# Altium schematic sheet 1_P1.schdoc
size 431 x 309 mm; Symbol: Sheet-Symbol_A4; Device: Sheet-Symbol_A4; @Page Name: P1; @Create Date: 2022-12-06; @Page Count: 3; @Page No: 1; @Project Name: MainBoard; @Schematic Name: Schematic1; @Update Date: 2022-12-29 15:32:21; Company: 嘉立创EDA; Page Size: A4; Version: V1.0
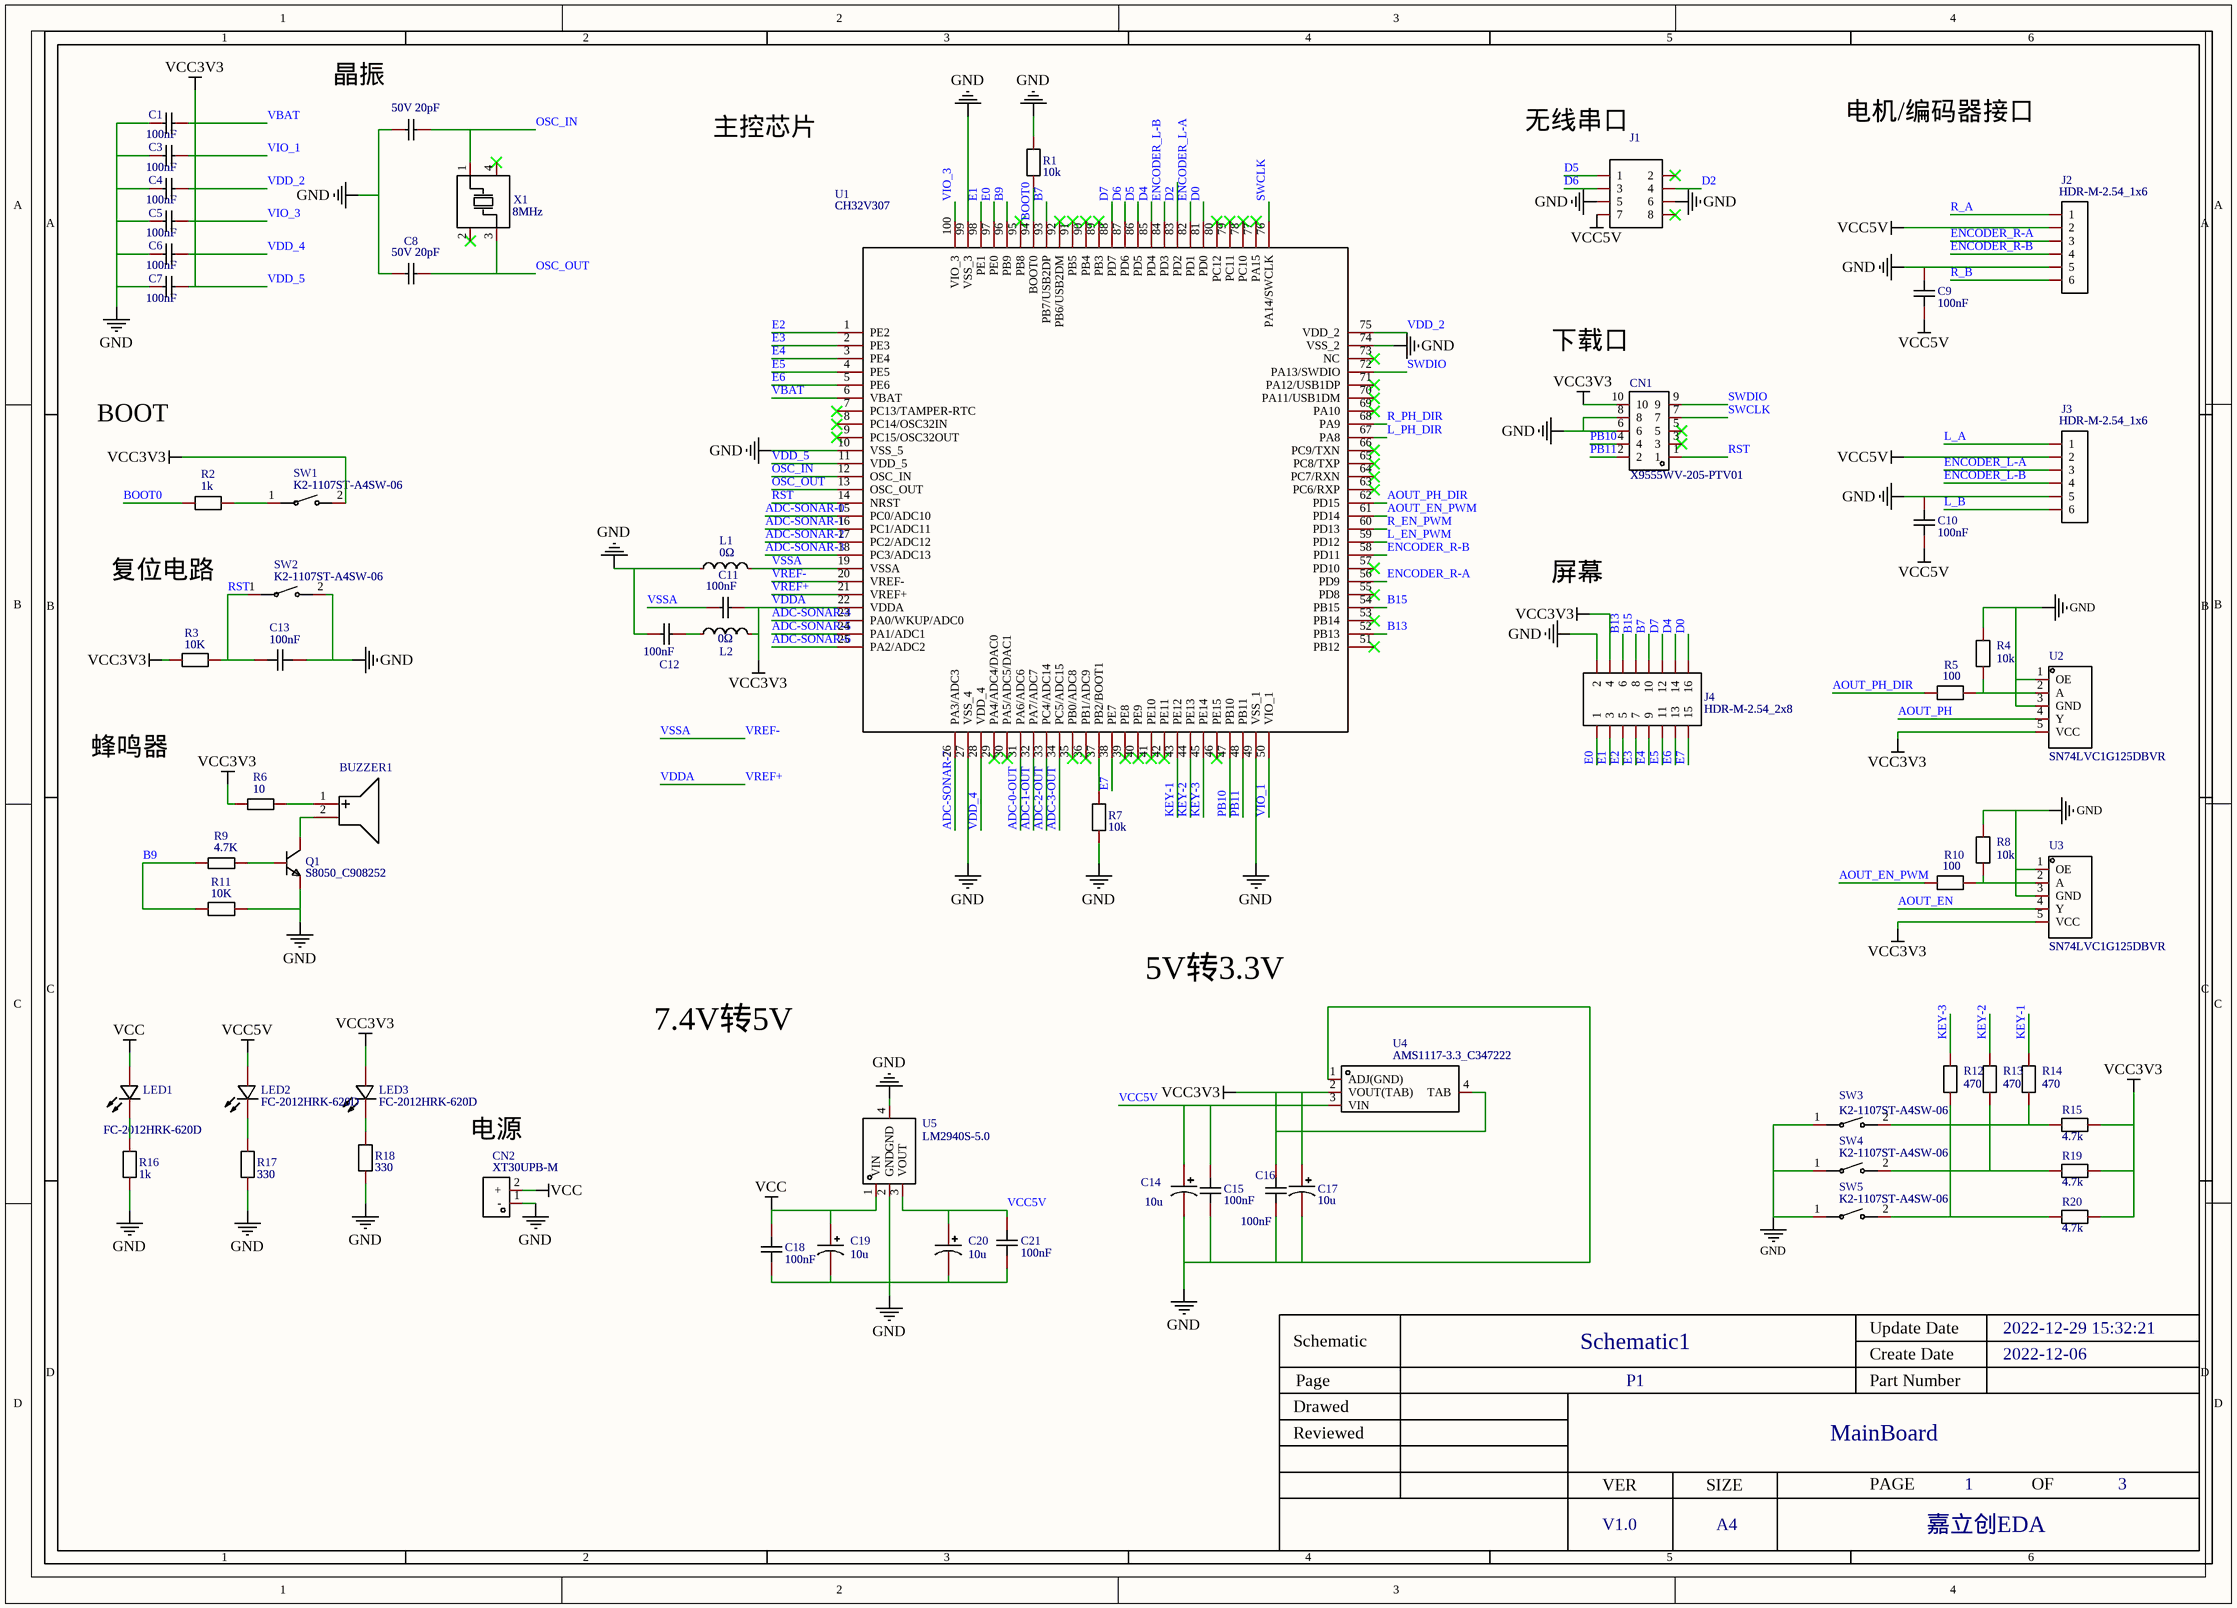
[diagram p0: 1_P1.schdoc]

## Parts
BUZZER1  2900Hz  [BUZ-TH_BD9.0-P5.00-D0.6-L-FD]  (value not drawn)
C1  100nF  [C0603]
C2  50V 20pF  [C0603]
C3  100nF  [C0603]
C4  100nF  [C0603]
C5  100nF  [C0603]
C6  100nF  [C0603]
C7  100nF  [C0603]
C8  50V 20pF  [C0603]
C9  100nF  [C0603]
C10  100nF  [C0603]
C11  100nF  [C0603]
C12  100nF  [C0603]
C13  100nF  [C0603]
C14  10u  [CASE-A_3216]
C15  100nF  [C0603]
C16  100nF  [C0603]
C17  10u  [CASE-A_3216]
C18  100nF  [C0603]
C19  10u  [CASE-A_3216]
C20  10u  [CASE-A_3216]
C21  100nF  [C0603]
CN1  X9555WV-205-PTV01  [CONN-TH_X9555WV-2-05-PTV01]
CN2  XT30UPB-M  [CONN-TH_XT30UPB-M]
J1  HDR-M-2.54_2x4  [HDR-M-2.54_2X4]  (value not drawn)
J2  HDR-M-2.54_1x6  [HDR-M-2.54_1X6]
J3  HDR-M-2.54_1x6  [HDR-M-2.54_1X6]
J4  HDR-M-2.54_2x8  [HDR-M-2.54_2X8]
L1  0Ω  [L0603]
L2  0Ω  [L0603]
LED1  FC-2012HRK-620D  [LED0805-RD_RED]
LED2  FC-2012HRK-620D  [LED0805-RD_RED]
LED3  FC-2012HRK-620D  [LED0805-RD_RED]
Q1  S8050_C908252  [SOT-23-3_L2.9-W1.3-P1.90-LS2.4-BR]
R1  10k  [R0603]
R2  1k  [R0603]
R3  10K  [R0603]
R4  10k  [R0603]
R5  100  [R0603]
R6  10  [R0603]
R7  10k  [R0603]
R8  10k  [R0603]
R9  4.7K  [R0603]
R10  100  [R0603]
R11  10K  [R0603]
R12  470  [R0603]
R13  470  [R0603]
R14  470  [R0603]
R15  4.7k  [R0603]
R16  1k  [R0603]
R17  330  [R0603]
R18  330  [R0603]
R19  4.7k  [R0603]
R20  4.7k  [R0603]
SW1  K2-1107ST-A4SW-06  [KEY-SMD_L6.2-W3.6-LS8.0]
SW2  K2-1107ST-A4SW-06  [KEY-SMD_L6.2-W3.6-LS8.0]
SW3  K2-1107ST-A4SW-06  [KEY-SMD_L6.2-W3.6-LS8.0]
SW4  K2-1107ST-A4SW-06  [KEY-SMD_L6.2-W3.6-LS8.0]
SW5  K2-1107ST-A4SW-06  [KEY-SMD_L6.2-W3.6-LS8.0]
U1  CH32V307  [CH32V307]
U2  SN74LVC1G125DBVR  [SOT-23-5_L3.0-W1.7-P0.95-LS2.8-BR]
U3  SN74LVC1G125DBVR  [SOT-23-5_L3.0-W1.7-P0.95-LS2.8-BR]
U4  AMS1117-3.3_C347222  [SOT-223_L6.7-W3.5-P2.30-BR]
U5  LM2940S-5.0  [SOT-223-3_L6.5-W3.4-P2.30-LS7.0-BR]
X1  8MHz  [OSC-SMD_4P-L5.0-W3.2-BL]

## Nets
GND: C1.2 C2.1 C3.2 C4.2 C5.2 C6.2 C7.2 C8.1 C9.1 C10.1 C12.2 C13.2 C14.2 C15.1 C16.1 C17.2 C18.1 C19.2 C20.2 C21.1 CN1.6 CN1.8 CN2.1(-) J1.5 J1.6 J2.5 J3.5 J4.2 L1.1 Q1.2(E) R1.1 R4.2 R7.1 R8.2 R11.1 R16.1 R17.1 R18.1 SW2.2 SW3.1 SW4.1 SW5.1 U1.10(VSS_5) U1.27(VSS_4) U1.49(VSS_1) U1.74(VSS_2) U1.99(VSS_3) U2.1(OE) U2.3(GND) U3.1(OE) U3.3(GND) U4.1(ADJ(GND)) U5.2(GND) U5.4(GND)
VBAT: C1.1 C3.1 C4.1 C5.1 C6.1 C7.1 C11.1 C16.2 C17.1 CN1.10 J4.4 L2.2 LED3.2(+) R3.2 R6.1 R15.1 R19.1 R20.1 SW1.2 U1.6(VBAT) U1.11(VDD_5) U1.21(VREF+) U1.22(VDDA) U1.28(VDD_4) U1.50(VIO_1) U1.75(VDD_2) U1.100(VIO_3) U2.5(VCC) U3.5(VCC) U4.2(VOUT(TAB)) U4.4(TAB)  [also labelled VCC3V3, VDD_2, VDD_4, VDD_5, VDDA, VIO_1, VIO_3, VREF+]
VCC: C18.2 C19.1 CN2.2(+) LED1.2(+) U5.1(VIN)
VCC5V: C9.2 C10.2 C14.1 C15.2 C20.1 C21.2 J1.7 J2.2 J3.2 LED2.2(+) U4.3(VIN) U5.3(VOUT)
ADC-0-OUT: U1.31(PA6/ADC6)
ADC-1-OUT: U1.32(PA7/ADC7)
ADC-2-OUT: U1.33(PC4/ADC14)
ADC-3-OUT: U1.34(PC5/ADC15)
ADC-SONAR-0: U1.15(PC0/ADC10)
ADC-SONAR-1: U1.16(PC1/ADC11)
ADC-SONAR-2: U1.17(PC2/ADC12)
ADC-SONAR-3: U1.18(PC3/ADC13)
ADC-SONAR-4: U1.23(PA0/WKUP/ADC0)
ADC-SONAR-5: U1.24(PA1/ADC1)
ADC-SONAR-6: U1.25(PA2/ADC2)
ADC-SONAR-7: U1.26(PA3/ADC3)
AOUT_EN: U3.4(Y)
AOUT_EN_PWM: R10.1 U1.61(PD14)
AOUT_PH: U2.4(Y)
AOUT_PH_DIR: R5.1 U1.62(PD15)
B7: J4.10 U1.93(PB7/USB2DP)
B9: R9.1 R11.2 U1.96(PB9)
B13: J4.6 U1.52(PB13)
B15: J4.8 U1.54(PB15)
BOOT0: R1.2 R2.2 U1.94(BOOT0)
D0: J4.16 U1.81(PD0)
D2: J1.4 U1.83(PD2)
D4: J4.14 U1.85(PD4)
D5: J1.1 U1.86(PD5)
D6: J1.3 U1.87(PD6)
D7: J4.12 U1.88(PD7)
E0: J4.1 U1.97(PE0)
E1: J4.3 U1.98(PE1)
E2: J4.5 U1.1(PE2)
E3: J4.7 U1.2(PE3)
E4: J4.9 U1.3(PE4)
E5: J4.11 U1.4(PE5)
E6: J4.13 U1.5(PE6)
E7: J4.15 U1.38(PE7)
ENCODER_L-A: J3.3 U1.82(PD1)
ENCODER_L-B: J3.4 U1.84(PD3)
ENCODER_R-A: J2.3 U1.56(PD9)
ENCODER_R-B: J2.4 U1.58(PD11)
KEY-1: R14.1 U1.43(PE12)
KEY-2: R13.1 U1.44(PE13)
KEY-3: R12.1 U1.45(PE14)
L_A: J3.1
L_B: J3.6
L_EN_PWM: U1.59(PD12)
L_PH_DIR: U1.67(PA8)
OSC_IN: C2.2 U1.12(OSC_IN) X1.1(OSC1)
OSC_OUT: C8.2 U1.13(OSC_OUT) X1.3(OSC2)
PB10: CN1.4 U1.47(PB10)
PB11: CN1.2 U1.48(PB11)
R_A: J2.1
R_B: J2.6
R_EN_PWM: U1.60(PD13)
R_PH_DIR: U1.68(PA9)
RST: C13.1 CN1.1 R3.1 SW2.1 U1.14(NRST)
SWCLK: CN1.7 U1.76(PA14/SWCLK)
SWDIO: CN1.9 U1.72(PA13/SWDIO)
VREF-: C11.2 L1.2 U1.19(VSSA) U1.20(VREF-)  [also labelled VSSA]
NetBUZZER1_1: BUZZER1.1(+) R6.2
NetBUZZER1_2: BUZZER1.2(-) Q1.3(C)
NetC12_1: C12.1 L2.1
NetLED1_1: LED1.1(-) R16.2
NetLED2_1: LED2.1(-) R17.2
NetLED3_1: LED3.1(-) R18.2
NetQ1_1: Q1.1(B) R9.2
NetR2_1: R2.1 SW1.1
NetR4_1: R4.1 R5.2 U2.2(A)
NetR7_2: R7.2 U1.37(PB2/BOOT1)
NetR8_1: R8.1 R10.2 U3.2(A)
NetR12_2: R12.2 R20.2 SW5.2
NetR13_2: R13.2 R19.2 SW4.2
NetR14_2: R14.2 R15.2 SW3.2

Not connected (* = marked no-connect by the designer): CN1 3* 5*; J1 2* 8*; U1 7(PC13/TAMPER-RTC)* 8(PC14/OSC32IN)* 9(PC15/OSC32OUT)* 29(PA4/ADC4/DAC0)* 30(PA5/ADC5/DAC1)* 35(PB0/ADC8)* 36(PB1/ADC9)* 39(PE8)* 40(PE9)* 41(PE10)* 42(PE11)* 46(PE15)* 51(PB12)* 53(PB14)* 55(PD8)* 57(PD10)* 63(PC6/RXP)* 64(PC7/RXN)* 65(PC8/TXP)* 66(PC9/TXN)* 69(PA10)* 70(PA11/USB1DM)* 71(PA12/USB1DP)* 73(NC)* 77(PA15)* 78(PC10)* 79(PC11)* 80(PC12)* 89(PB3)* 90(PB4)* 91(PB5)* 92(PB6/USB2DM)* 95(PB8)*; X1 2(GND)* 4(GND)*

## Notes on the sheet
- 晶振
- 电机/编码器接口
- 主控芯片
- (near J1) 无线串口
- 下载口
- BOOT
- 复位电路
- 屏幕
- 蜂鸣器
- 7.4V转5V
- 5V转3.3V
- (near CN2) 电源

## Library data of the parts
BUZZER1 = Cy-9055-5029: 驱动方式:有源(内含驱动线路);构造类型:电磁式;额定电压:5V;工作电压:4V~7V;频率:2900Hz;声压(SPL):85dB@5V,10cm;直径(φD):9mm;高度:6mm;; Manufacturer: CY(超音); Add into BOM: yes; Technology Type: 电磁式; Rated Voltage: 5V; Operating Voltage: 4V~7V
C1 C3-C7 C11 C12 = CC0603JRNPO9BN220: Manufacturer: YAGEO; Symbol: 50V 20pF; Convert to PCB: yes
C2 C8 = CC0603JRNPO9BN220: Manufacturer: YAGEO; Convert to PCB: yes
C9 C10 C13 = CL10B104KC8NNNC: Manufacturer: SAMSUNG; Convert to PCB: yes
C14 C17 C19 C20 = 10u: Convert to PCB: yes
C15 C16 C18 C21 = 100nf: Convert to PCB: yes
CN1 = X9555WV-2×05-PTV01: Manufacturer: XKB Connectivity; Convert to PCB: yes
CN2 = XT30UPB-M: Manufacturer: Changzhou Amass Elec; Convert to PCB: yes
J1 = HDR-M-2.54_2x4: Convert to PCB: yes
J2 J3 = HDR-M-2.54_1x6: Convert to PCB: yes
J4 = HDR-M-2.54_2x8: Convert to PCB: yes
L1 L2 = CBG160808U000T: Manufacturer: FH; Convert to PCB: yes
LED1-LED3 = FC-2012HRK-620D: Manufacturer: NATIONSTAR; Convert to PCB: yes
Q1 = S8050: Manufacturer: FUXINSEMI; Convert to PCB: yes
R1 R7 = 10k: Convert to PCB: yes
R2 = 1k: Convert to PCB: yes
R3 R11 = RC0603FR-0710KL: Manufacturer: YAGEO; Convert to PCB: yes
R4 R5 R8 R10 = 100: Convert to PCB: yes
R6 = RC0603JR-0710RL: Manufacturer: YAGEO; Convert to PCB: yes
R9 = RC0603FR-074K7L: Manufacturer: YAGEO; Convert to PCB: yes
R12-R15 R17-R20 = 330: Convert to PCB: yes
R16 = 1k: Convert to PCB: yes; NUMBER: 2
SW1-SW5 = K2-1107ST-A4SW-06: Manufacturer: Rectangular Connectors - Contacts; Convert to PCB: yes
U1 = CH32V307: Convert to PCB: yes
U2 U3 = SN74LVC1G125DBVR: 逻辑电路的归属系列:74LVC;逻辑类型:缓冲器，非反向;元件数:1;每元件位数:1;; Manufacturer: TI(德州仪器); Add into BOM: yes; Number of Elements: 1; Output Type: 三态; Current - Output High, Low: 32mA、32mA; Voltage - Supply: 1.65V ~ 5.5V
U4 = AMS1117-3.3: Manufacturer: Youtai Semiconductor Co., Ltd.; Convert to PCB: yes
U5 = LM2940S-5.0: 输出类型:-;; Manufacturer: HTC; Add into BOM: yes
X1 = SMD-5032_4P8M20pf20ppm: Manufacturer: TAE; Convert to PCB: yes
